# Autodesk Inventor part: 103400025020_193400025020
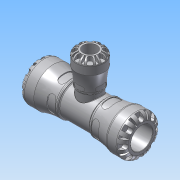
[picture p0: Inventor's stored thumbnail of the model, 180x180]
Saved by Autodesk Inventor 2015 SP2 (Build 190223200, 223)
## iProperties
Created: 2016-12
Part Number: 103400025020_193400025020
Material: PVC-Piping
Description: PLASSON REDUCING TEE 25X20X25 SERIES 1
Document SubType Name: Modeling
Designer: KIM
Mass: 664.223 g
Surface Area: 733.008 cm^2
Volume: 474.445 cm^3
Density: 1.4 g/cm^3
Appearance: Smooth - White
Author: KIM
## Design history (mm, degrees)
derived "1034.ipt"
feature "Solid1::1034.ipt"
tag "TaggingFeature1"
body "Solid1"
other parameters: "d1" = 20.16, "d2" = 25, "d3" = 31.25, "d4" = 47, "d8" = 39.95, "d13" = 6.3, "d14" = 6.3, "d15" = 0, "d17" = 360 deg, "d19" = 8 deg, "d20" = 0.5, "d21" = 0.5, "d22" = 8 deg, "d24" = 0, "d26" = 360 deg, "d33" = 4.7, "d43" = 36.66, "d51" = 0.47, "d54" = 8.75, "d55" = 5.5, "d57" = 12.348, "d58" = 0, "d74" = 0, "d77" = 2.08333, "d78" = 48, "d79" = 36.66, "d80" = 134, "d82" = 0.5, "d115" = 360 deg, "d139" = 6.3, "d140" = 0, "d142" = 360 deg, "d207" = 90 deg, "d209" = 19.32, "d211" = 25, "d212" = 41, "d213" = 34.85, "d215" = 31.98, "d216" = 1.66667, "d217" = 46, "d225" = 73, "d226" = 46, "d228" = 7.4375, "d229" = 6.4, "d233" = 6.4, "d234" = 0, "d236" = 360 deg, "d238" = 8 deg, "d239" = 8 deg, "d240" = 0.5, "d241" = 0.5, "d243" = 0, "d245" = 360 deg, "d247" = 0.94, "d248" = 2.88, "d249" = 2.76, "d250" = 5.95, "d252" = 7, "d253" = 4.6, "d254" = 12.348, "d255" = 0, "d257" = 360 deg, "d259" = 0.5, "d261" = 0, "d262" = 0.94, "d264" = 0, "d266" = 0, "d267" = 0.47, "d_" = 25, "E_" = 47, "l_" = 48, "A_" = 73, "H_" = 134, "E_1" = 41, "l_1" = 46, "d9" = 7.875, "d11" = 47, "d12" = 31.25, "d230" = 41, "d231" = 25, "d232" = 8
